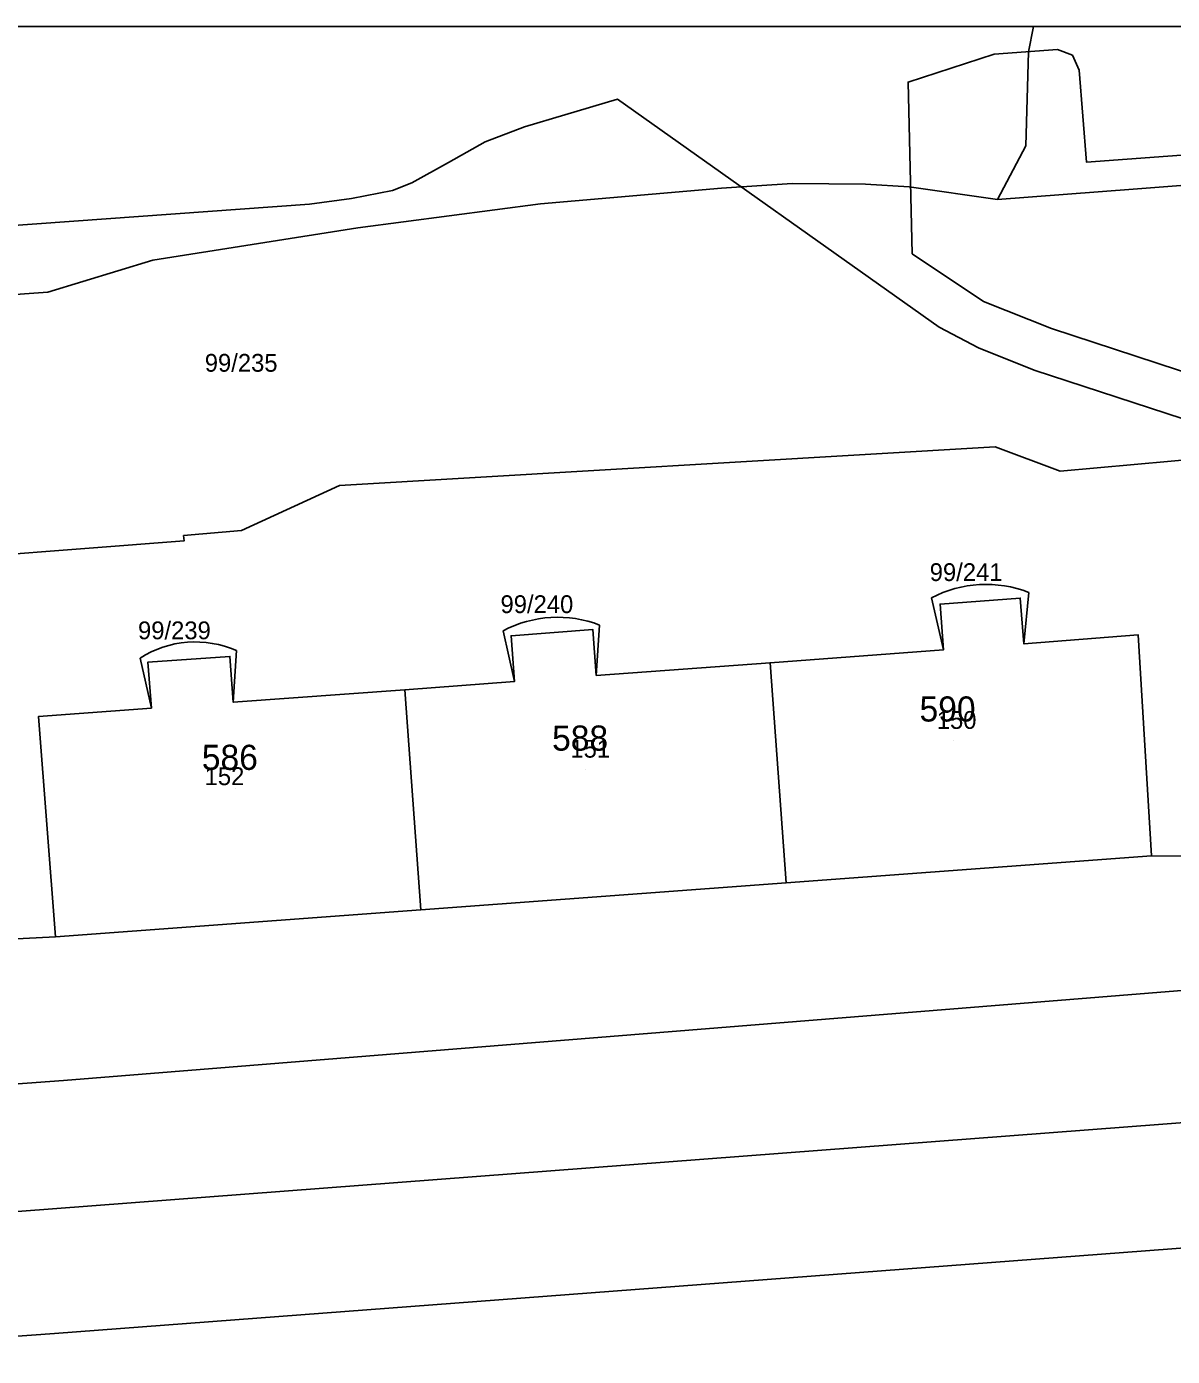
# Model space of a CAD drawing. Extents: x -873642 to -872917, y -1012962 to -1012567.
# Drawn here: x -873408.4 to -873353.7, y -1012631 to -1012567.5 of the extents above; entities that cross this region are included whole.
import ezdxf

# ---------------------------------------------------------------- set-up
doc = ezdxf.new("R2010")
doc.units = 0
for name, color, linetype in [('adresni_misto', 7, 'Continuous'), ('cisla_parcelni_kn', 7, 'Continuous'), ('cislo_domovni', 7, 'Continuous'), ('osy_ulic', 7, 'Continuous'), ('parcely_kn', 7, 'Continuous'), ('stavebni_objekty_bydleni', 7, 'Continuous'), ('TRASY - zamereno', 7, 'Continuous')]:
    doc.layers.add(name, color=color, linetype=linetype)

msp = doc.modelspace()

# ---------------------------------------------------------------- linework, layer by layer
at = {"layer": 'adresni_misto'}
for p, q in [((-873364.17, -1012601.6), (-873364.17, -1012601.6)), ((-873381.72, -1012602.99), (-873381.72, -1012602.99)), ((-873398.45, -1012603.91), (-873398.45, -1012603.91))]:
    msp.add_line(p, q, dxfattribs=at)
at = {"layer": 'osy_ulic'}
msp.add_lwpolyline([(-872916.927, -1012586.659), (-872957.62, -1012590.24), (-872977.73, -1012591.46), (-872994.83, -1012592.51), (-873031.96, -1012595.34), (-873059.56, -1012597.3), (-873096.52, -1012600.28), (-873281.07, -1012614.36), (-873481.95, -1012629.68)], dxfattribs=at)
at = {"layer": 'parcely_kn'}
msp.add_line((-873340.542, -1012567.5), (-873415.236, -1012567.5), dxfattribs=at)
msp.add_line((-873340.542, -1012567.5), (-873415.236, -1012567.5), dxfattribs=at)
for points in [[(-873340.31, -1012572.69), (-873357.79, -1012573.98), (-873358.14, -1012569.58), (-873358.47, -1012568.87), (-873359.18, -1012568.59), (-873362.21, -1012568.82), (-873366.32, -1012570.15), (-873366.12, -1012578.35), (-873362.71, -1012580.63), (-873359.47, -1012581.92), (-873345.34, -1012586.56)], [(-873345.34, -1012586.56), (-873359.47, -1012581.92), (-873362.71, -1012580.63), (-873366.12, -1012578.35), (-873366.32, -1012570.15), (-873362.21, -1012568.82), (-873359.18, -1012568.59), (-873358.47, -1012568.87), (-873358.14, -1012569.58), (-873357.79, -1012573.98), (-873340.31, -1012572.69)], [(-873340.31, -1012572.69), (-873357.79, -1012573.98), (-873358.14, -1012569.58), (-873358.47, -1012568.87), (-873359.18, -1012568.59), (-873362.21, -1012568.82), (-873366.32, -1012570.15), (-873366.12, -1012578.35), (-873362.71, -1012580.63), (-873359.47, -1012581.92), (-873345.34, -1012586.56)], [(-873345.34, -1012586.56), (-873359.47, -1012581.92), (-873362.71, -1012580.63), (-873366.12, -1012578.35), (-873366.32, -1012570.15), (-873362.21, -1012568.82), (-873359.18, -1012568.59), (-873358.47, -1012568.87), (-873358.14, -1012569.58), (-873357.79, -1012573.98), (-873340.31, -1012572.69)], [(-873425.82, -1012578.21), (-873394.9, -1012575.99), (-873392.9, -1012575.72), (-873390.94, -1012575.33), (-873390.02, -1012574.96), (-873388.27, -1012573.99), (-873386.52, -1012573.01), (-873384.64, -1012572.29), (-873382.71, -1012571.72), (-873380.19, -1012570.97), (-873364.83, -1012581.86), (-873362.95, -1012582.85), (-873360.29, -1012583.92), (-873348.45, -1012587.78), (-873359.06, -1012588.74), (-873362.16, -1012587.58), (-873393.48, -1012589.42), (-873398.16, -1012591.58), (-873400.92, -1012591.82), (-873400.89, -1012592.06), (-873415.35, -1012593.18)], [(-873425.82, -1012578.21), (-873394.9, -1012575.99), (-873392.9, -1012575.72), (-873390.94, -1012575.33), (-873390.02, -1012574.96), (-873388.27, -1012573.99), (-873386.52, -1012573.01), (-873384.64, -1012572.29), (-873382.71, -1012571.72), (-873380.19, -1012570.97), (-873364.83, -1012581.86), (-873362.95, -1012582.85), (-873360.29, -1012583.92), (-873348.45, -1012587.78)], [(-873425.82, -1012578.21), (-873394.9, -1012575.99), (-873392.9, -1012575.72), (-873390.94, -1012575.33), (-873390.02, -1012574.96), (-873388.27, -1012573.99), (-873386.52, -1012573.01), (-873384.64, -1012572.29), (-873382.71, -1012571.72), (-873380.19, -1012570.97), (-873364.83, -1012581.86), (-873362.95, -1012582.85), (-873360.29, -1012583.92), (-873348.45, -1012587.78), (-873359.06, -1012588.74), (-873362.16, -1012587.58), (-873393.48, -1012589.42), (-873398.16, -1012591.58), (-873400.92, -1012591.82), (-873400.89, -1012592.06), (-873415.35, -1012593.18)], [(-873425.82, -1012578.21), (-873394.9, -1012575.99), (-873392.9, -1012575.72), (-873390.94, -1012575.33), (-873390.02, -1012574.96), (-873388.27, -1012573.99), (-873386.52, -1012573.01), (-873384.64, -1012572.29), (-873382.71, -1012571.72), (-873380.19, -1012570.97), (-873364.83, -1012581.86), (-873362.95, -1012582.85), (-873360.29, -1012583.92), (-873348.45, -1012587.78)], [(-873415.35, -1012593.18), (-873400.89, -1012592.06), (-873400.92, -1012591.82), (-873398.16, -1012591.58), (-873393.48, -1012589.42), (-873362.16, -1012587.58), (-873359.06, -1012588.74), (-873348.45, -1012587.78)], [(-873415.35, -1012593.18), (-873400.89, -1012592.06), (-873400.92, -1012591.82), (-873398.16, -1012591.58), (-873393.48, -1012589.42), (-873362.16, -1012587.58), (-873359.06, -1012588.74), (-873348.45, -1012587.78)], [(-873337.45, -1012589.33), (-873336.83, -1012591.74), (-873342.29, -1012592.14), (-873343.3, -1012592.22), (-873344.05, -1012592.43), (-873344.43, -1012592.84), (-873344.58, -1012593.07), (-873344.56, -1012593.61), (-873343.77, -1012604.58), (-873345.93, -1012604.83), (-873345.77, -1012606.73), (-873347.87, -1012606.83), (-873348.04, -1012604.94), (-873352.63, -1012605.24), (-873352.69, -1012607.13), (-873354.69, -1012607.11), (-873355.33, -1012596.55), (-873360.78, -1012596.99), (-873360.55, -1012594.53)], [(-873337.45, -1012589.33), (-873336.83, -1012591.74), (-873342.29, -1012592.14), (-873343.3, -1012592.22), (-873344.05, -1012592.43), (-873344.43, -1012592.84), (-873344.58, -1012593.07), (-873344.56, -1012593.61), (-873343.77, -1012604.58), (-873345.93, -1012604.83), (-873345.77, -1012606.73), (-873347.87, -1012606.83), (-873348.04, -1012604.94), (-873352.63, -1012605.24), (-873352.69, -1012607.13), (-873354.69, -1012607.11), (-873355.33, -1012596.55), (-873360.78, -1012596.99), (-873360.55, -1012594.53)], [(-873365.2, -1012594.79), (-873364.63, -1012597.28), (-873372.91, -1012597.89), (-873381.21, -1012598.5), (-873381.05, -1012596.09)], [(-873365.2, -1012594.79), (-873364.63, -1012597.28), (-873372.91, -1012597.89), (-873381.21, -1012598.5), (-873381.05, -1012596.09)], [(-873364.79, -1012595.09), (-873364.63, -1012597.28), (-873365.2, -1012594.79)], [(-873364.79, -1012595.09), (-873364.63, -1012597.28), (-873365.2, -1012594.79)], [(-873360.55, -1012594.53), (-873360.78, -1012596.99), (-873360.96, -1012594.8), (-873364.79, -1012595.09)], [(-873360.55, -1012594.53), (-873360.78, -1012596.99), (-873360.96, -1012594.8), (-873364.79, -1012595.09)], [(-873381.05, -1012596.09), (-873381.21, -1012598.5), (-873381.37, -1012596.31), (-873385.28, -1012596.6)], [(-873381.05, -1012596.09), (-873381.21, -1012598.5), (-873381.37, -1012596.31), (-873385.28, -1012596.6)], [(-873385.65, -1012596.36), (-873385.12, -1012598.79), (-873390.36, -1012599.18), (-873398.55, -1012599.78), (-873398.39, -1012597.31)], [(-873385.65, -1012596.36), (-873385.12, -1012598.79), (-873390.36, -1012599.18), (-873398.55, -1012599.78), (-873398.39, -1012597.31)], [(-873385.28, -1012596.6), (-873385.12, -1012598.79), (-873385.65, -1012596.36)], [(-873385.28, -1012596.6), (-873385.12, -1012598.79), (-873385.65, -1012596.36)], [(-873398.39, -1012597.31), (-873398.55, -1012599.78), (-873398.71, -1012597.59), (-873402.62, -1012597.86)], [(-873398.39, -1012597.31), (-873398.55, -1012599.78), (-873398.71, -1012597.59), (-873402.62, -1012597.86)], [(-873143.44, -1012597.91), (-873216.55, -1012603.73), (-873279.94, -1012608.27), (-873348.3, -1012613.15), (-873406.66, -1012617.85), (-873469.84, -1012622.48), (-873491.33, -1012623.66), (-873566.46, -1012629.92), (-873583.11, -1012630.93), (-873584.28, -1012631.65), (-873606.27, -1012634.41), (-873608.98, -1012633.05), (-873615.37, -1012633.09), (-873642.294, -1012633.957)], [(-873403, -1012597.67), (-873402.46, -1012600.06), (-873407.85, -1012600.46), (-873407.04, -1012610.98), (-873418.47, -1012611.57), (-873418.89, -1012601.06), (-873421.55, -1012601.17), (-873427, -1012601.56), (-873426.85, -1012599.05)], [(-873403, -1012597.67), (-873402.46, -1012600.06), (-873407.85, -1012600.46), (-873407.04, -1012610.98), (-873418.47, -1012611.57), (-873418.89, -1012601.06), (-873421.55, -1012601.17), (-873427, -1012601.56), (-873426.85, -1012599.05)], [(-873402.62, -1012597.86), (-873402.46, -1012600.06), (-873403, -1012597.67)], [(-873402.62, -1012597.86), (-873402.46, -1012600.06), (-873403, -1012597.67)], [(-873642.294, -1012646.913), (-873615.37, -1012644.94), (-873586.69, -1012643.34), (-873548.73, -1012640.58), (-873509.03, -1012637.61), (-873492.26, -1012636.3), (-873470.15, -1012634.51), (-873407.08, -1012629.93), (-873286.69, -1012620.81), (-873282.45, -1012620.53), (-873276.73, -1012620.14), (-873273.72, -1012619.94), (-873079.43, -1012607.12)], [(-873352.69, -1012607.13), (-873354.69, -1012607.11), (-873372.14, -1012608.4), (-873389.59, -1012609.69), (-873407.04, -1012610.98), (-873418.47, -1012611.57)], [(-873352.69, -1012607.13), (-873354.69, -1012607.11), (-873372.14, -1012608.4), (-873389.59, -1012609.69), (-873407.04, -1012610.98), (-873418.47, -1012611.57)], [(-873407.08, -1012629.93), (-873286.69, -1012620.81), (-873282.45, -1012620.53), (-873276.73, -1012620.14), (-873273.72, -1012619.94), (-873079.43, -1012607.12)], [(-873407.08, -1012629.93), (-873286.69, -1012620.81), (-873282.45, -1012620.53), (-873276.73, -1012620.14), (-873273.72, -1012619.94), (-873079.43, -1012607.12)], [(-873469.84, -1012622.48), (-873406.66, -1012617.85), (-873348.3, -1012613.15)], [(-873469.84, -1012622.48), (-873406.66, -1012617.85), (-873348.3, -1012613.15)], [(-873095.85, -1012678.72), (-873263.61, -1012691.39), (-873266.56, -1012691.78), (-873320.85, -1012695.55), (-873397.76, -1012701.2), (-873419.57, -1012702.63), (-873457.18, -1012705.12), (-873461.77, -1012705), (-873467.35, -1012700.29), (-873470.31, -1012685.53), (-873471.34, -1012679.34), (-873473.95, -1012664.84), (-873474.55, -1012659.21), (-873476.91, -1012642.49), (-873476.25, -1012638.16), (-873474.09, -1012635.88), (-873470.15, -1012634.51), (-873407.08, -1012629.93)], [(-873095.85, -1012678.72), (-873263.61, -1012691.39), (-873266.56, -1012691.78), (-873320.85, -1012695.55), (-873397.76, -1012701.2), (-873419.57, -1012702.63), (-873457.18, -1012705.12), (-873461.77, -1012705), (-873467.35, -1012700.29), (-873470.31, -1012685.53), (-873471.34, -1012679.34), (-873473.95, -1012664.84), (-873474.55, -1012659.21), (-873476.91, -1012642.49), (-873476.25, -1012638.16), (-873474.09, -1012635.88), (-873470.15, -1012634.51), (-873407.08, -1012629.93)]]:
    msp.add_lwpolyline(points, dxfattribs=at)
for points in [[(-873372.91, -1012597.89), (-873364.63, -1012597.28), (-873364.79, -1012595.09), (-873360.96, -1012594.8), (-873360.78, -1012596.99), (-873355.33, -1012596.55), (-873354.69, -1012607.11), (-873372.14, -1012608.4)], [(-873372.91, -1012597.89), (-873364.63, -1012597.28), (-873364.79, -1012595.09), (-873360.96, -1012594.8), (-873360.78, -1012596.99), (-873355.33, -1012596.55), (-873354.69, -1012607.11), (-873372.14, -1012608.4)], [(-873390.36, -1012599.18), (-873385.12, -1012598.79), (-873385.28, -1012596.6), (-873381.37, -1012596.31), (-873381.21, -1012598.5), (-873372.91, -1012597.89), (-873372.14, -1012608.4), (-873389.59, -1012609.69)], [(-873390.36, -1012599.18), (-873385.12, -1012598.79), (-873385.28, -1012596.6), (-873381.37, -1012596.31), (-873381.21, -1012598.5), (-873372.91, -1012597.89), (-873372.14, -1012608.4), (-873389.59, -1012609.69)], [(-873398.55, -1012599.78), (-873390.36, -1012599.18), (-873389.59, -1012609.69), (-873407.04, -1012610.98), (-873407.85, -1012600.46), (-873402.46, -1012600.06), (-873402.62, -1012597.86), (-873398.71, -1012597.59)], [(-873398.55, -1012599.78), (-873390.36, -1012599.18), (-873389.59, -1012609.69), (-873407.04, -1012610.98), (-873407.85, -1012600.46), (-873402.46, -1012600.06), (-873402.62, -1012597.86), (-873398.71, -1012597.59)]]:
    msp.add_lwpolyline(points, close=True, dxfattribs=at)
for centre, radius, start, end in [((-873362.588, -1012599.789), 5.641, 68.81736, 117.58325), ((-873362.588, -1012599.789), 5.641, 68.81736, 117.58325), ((-873362.588, -1012599.789), 5.641, 68.81736, 117.58325), ((-873362.588, -1012599.789), 5.641, 68.81736, 117.58325), ((-873383.052, -1012601.301), 5.583, 68.9847, 117.73362), ((-873383.052, -1012601.301), 5.583, 68.98425, 117.73407), ((-873383.052, -1012601.301), 5.583, 68.9847, 117.73362), ((-873383.052, -1012601.301), 5.583, 68.98425, 117.73407), ((-873400.359, -1012601.792), 4.895, 66.28076, 122.6497), ((-873400.359, -1012601.792), 4.895, 66.28065, 122.64981), ((-873400.359, -1012601.792), 4.895, 66.28076, 122.6497), ((-873400.359, -1012601.792), 4.895, 66.28065, 122.64981)]:
    msp.add_arc(centre, radius, start, end, dxfattribs=at)
at = {"layer": 'stavebni_objekty_bydleni'}
for points in [[(-873372.14, -1012608.4), (-873372.91, -1012597.89), (-873364.63, -1012597.28), (-873364.79, -1012595.09), (-873360.96, -1012594.8), (-873360.78, -1012596.99), (-873355.33, -1012596.55), (-873354.69, -1012607.11)], [(-873390.36, -1012599.18), (-873385.12, -1012598.79), (-873385.28, -1012596.6), (-873381.37, -1012596.31), (-873381.21, -1012598.5), (-873372.91, -1012597.89), (-873372.14, -1012608.4), (-873389.59, -1012609.69)], [(-873402.62, -1012597.86), (-873398.71, -1012597.59), (-873398.55, -1012599.78), (-873390.36, -1012599.18), (-873389.59, -1012609.69), (-873407.04, -1012610.98), (-873407.85, -1012600.46), (-873402.46, -1012600.06)]]:
    msp.add_lwpolyline(points, close=True, dxfattribs=at)
at = {"layer": 'TRASY - zamereno'}
for p, q in [((-873360.57, -1012568.7), (-873360.322, -1012567.5)), ((-873360.69, -1012573.19), (-873360.57, -1012568.7)), ((-873362.04, -1012575.76), (-873360.69, -1012573.19)), ((-873355.56, -1012575.27), (-873344.91, -1012574.45)), ((-873375.23, -1012575.22), (-873371.86, -1012575)), ((-873371.86, -1012575), (-873368.35, -1012575.02)), ((-873368.35, -1012575.02), (-873366.27, -1012575.15)), ((-873383.87, -1012575.96), (-873375.23, -1012575.22)), ((-873366.27, -1012575.15), (-873362.04, -1012575.76)), ((-873362.04, -1012575.76), (-873355.56, -1012575.27)), ((-873392.6, -1012577.12), (-873383.87, -1012575.96)), ((-873402.39, -1012578.66), (-873392.6, -1012577.12)), ((-873407.4, -1012580.18), (-873402.39, -1012578.66)), ((-873416.45, -1012580.83), (-873407.4, -1012580.18))]:
    msp.add_line(p, q, dxfattribs=at)

# ---------------------------------------------------------------- texts
at = {"layer": 'cisla_parcelni_kn'}
for s, p in [('99/235', (-873399.908, -1012583.988)), ('99/235', (-873399.908, -1012583.988)), ('99/241', (-873365.283, -1012593.988)), ('99/241', (-873365.283, -1012593.988)), ('99/240', (-873385.783, -1012595.519)), ('99/240', (-873385.783, -1012595.519)), ('99/239', (-873403.096, -1012596.769)), ('99/239', (-873403.096, -1012596.769)), ('150', (-873364.946, -1012601.05)), ('150', (-873364.946, -1012601.05)), ('151', (-873382.446, -1012602.425)), ('151', (-873382.446, -1012602.425)), ('152', (-873399.915, -1012603.738)), ('152', (-873399.915, -1012603.738))]:
    msp.add_text(s, height=0.85, dxfattribs=at).set_placement(p)
at = {"layer": 'cislo_domovni'}
for s, p in [('590', (-873365.77, -1012600.7)), ('588', (-873383.32, -1012602.09)), ('586', (-873400.05, -1012603.01))]:
    msp.add_text(s, height=1.2, dxfattribs=at).set_placement(p)

doc.saveas('drawing.dxf')
